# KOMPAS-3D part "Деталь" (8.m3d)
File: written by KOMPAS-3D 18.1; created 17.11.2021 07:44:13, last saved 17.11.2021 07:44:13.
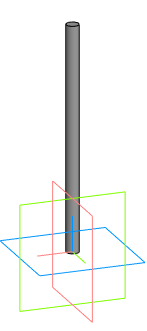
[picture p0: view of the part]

Document properties: Автор: 111; Полное имя файла: C:\Users\admin\Desktop\ffb\8.m3d

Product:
- Part/product: Деталь
    Масса: 0.0237672

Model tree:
1. Эскиз:1
2. Элемент выдавливания:1
     Расстояние 1 = 107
